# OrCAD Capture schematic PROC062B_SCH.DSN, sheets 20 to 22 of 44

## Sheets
20 19. EEPROM & PRESENCE DETECTION: size C; title: EEPROM,PRESENCE DETECTION & TEMP SENSOR
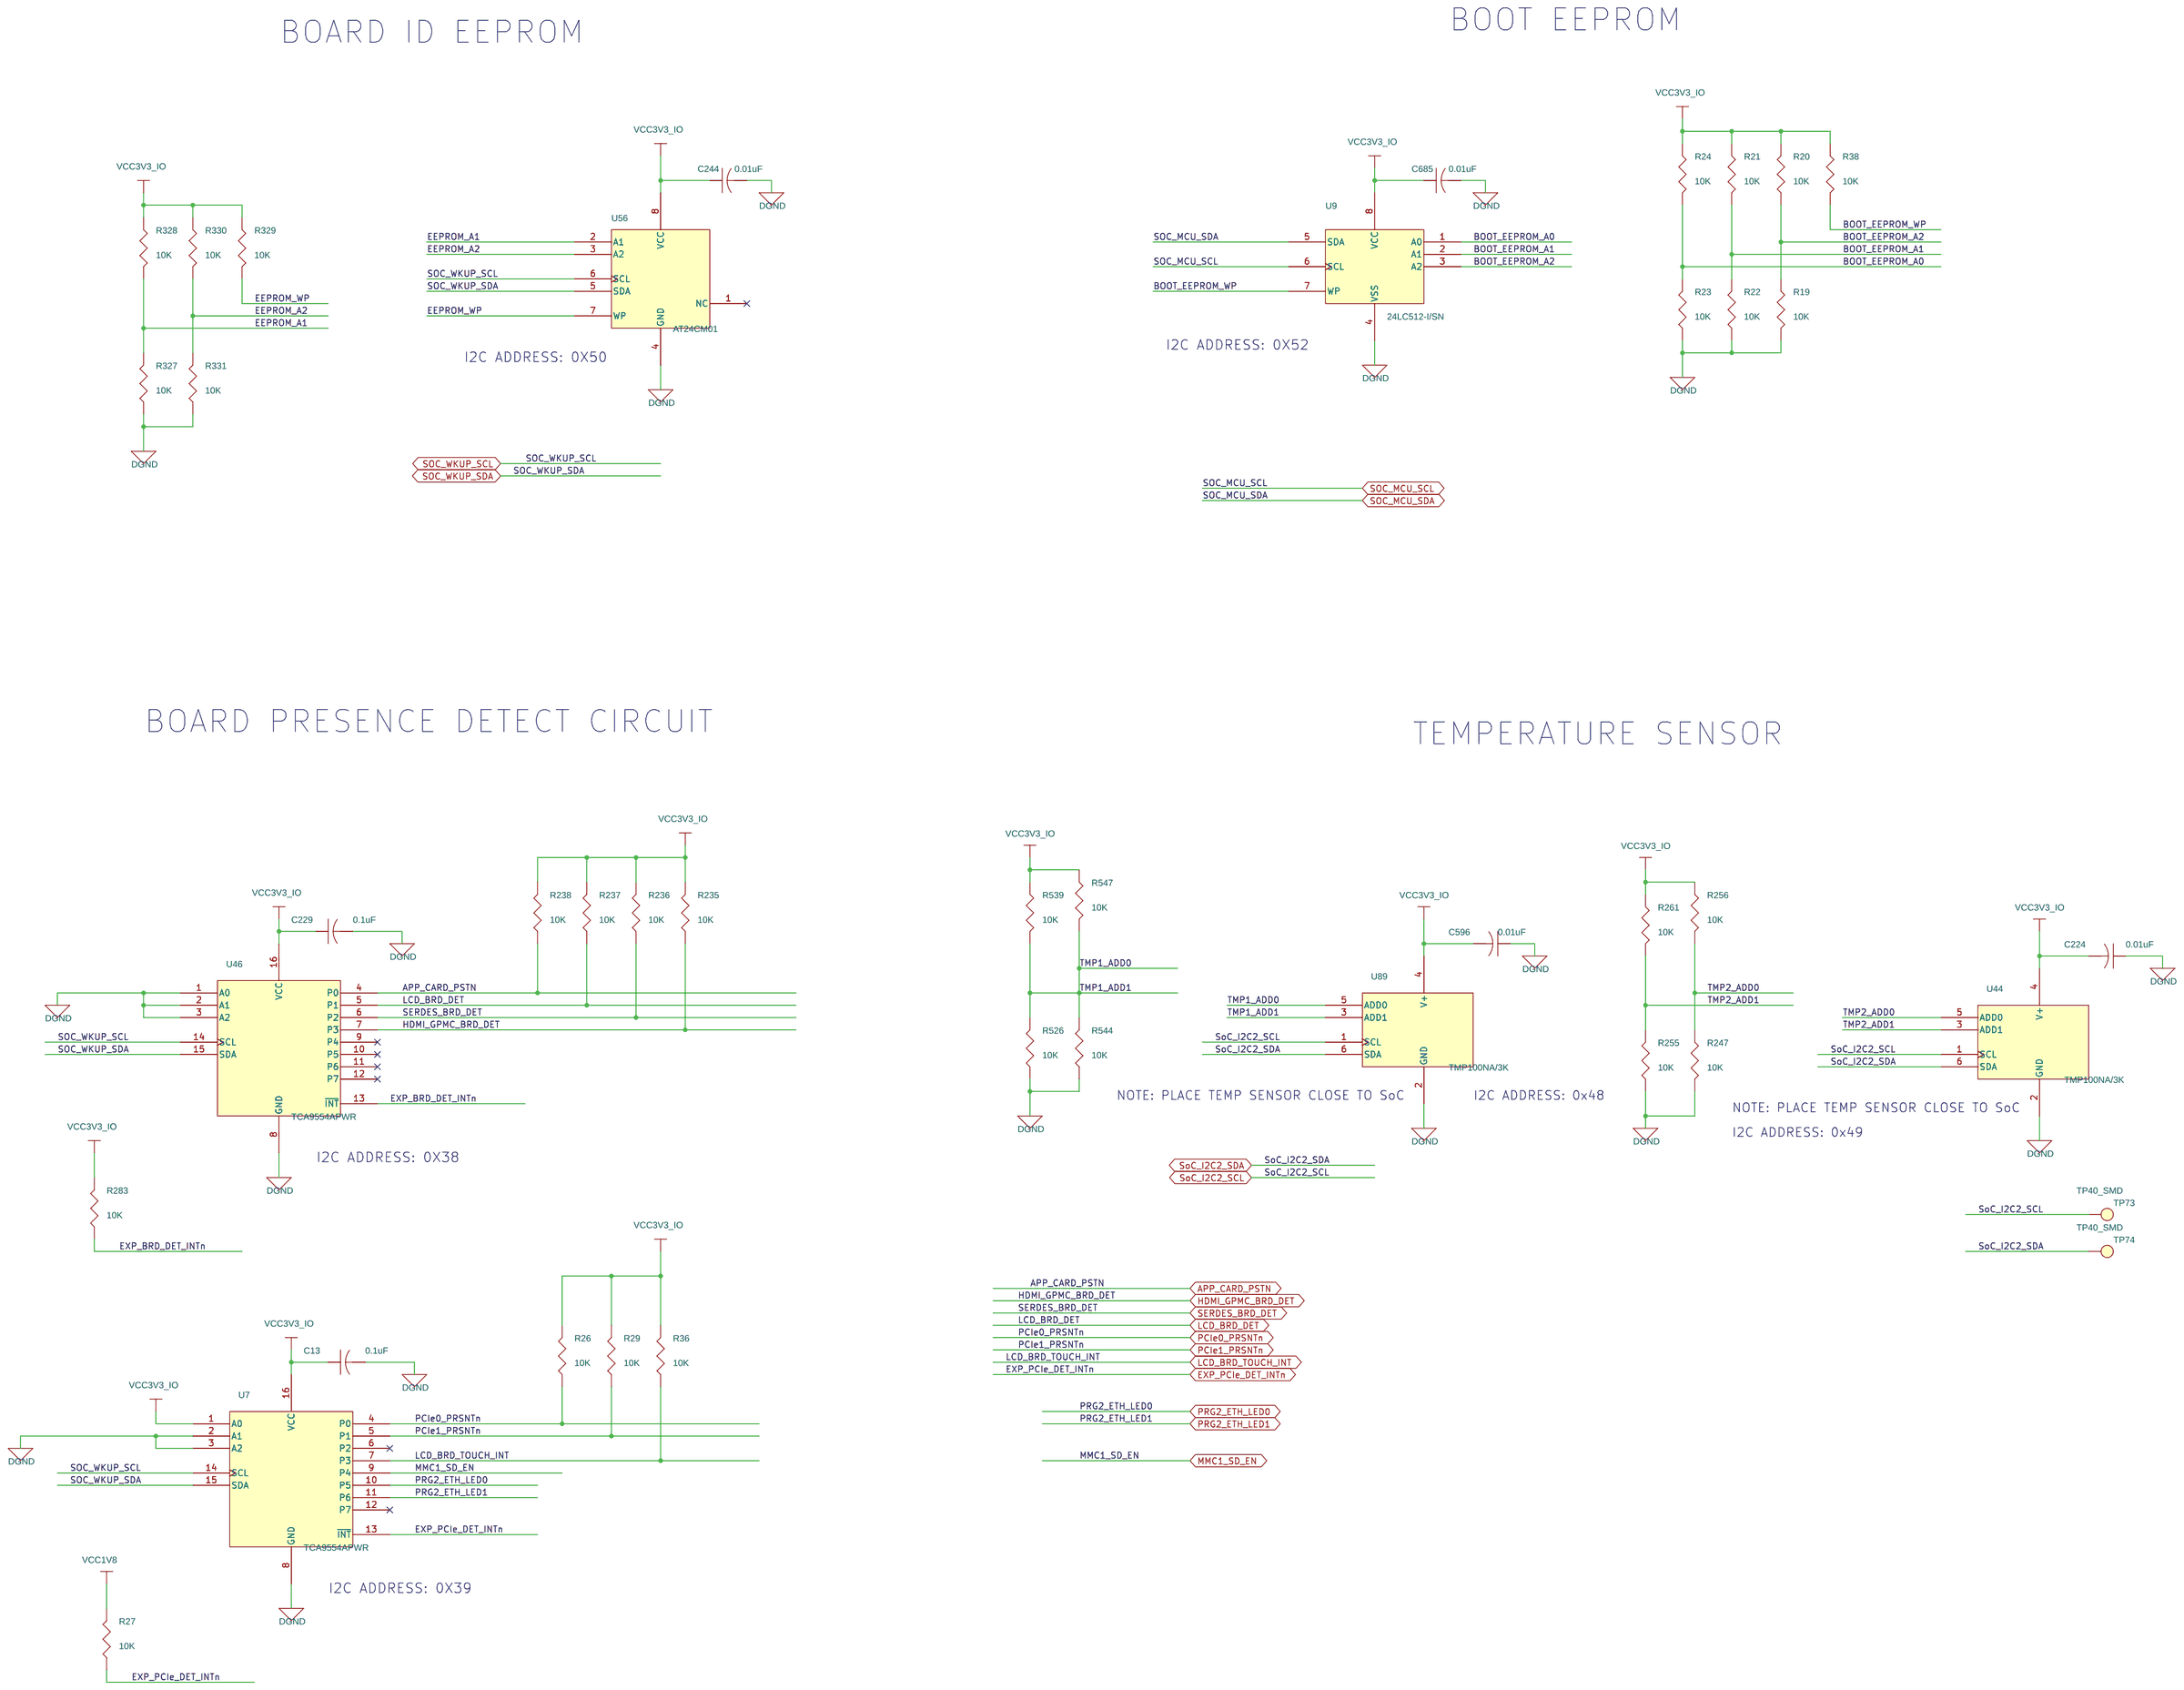
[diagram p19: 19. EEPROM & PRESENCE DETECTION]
21 20. RGMII_1 ETHERNET PHY- ICSSG: size C; title: RGMII ETHERNET PHY - ICSSG PRG2_PRU0
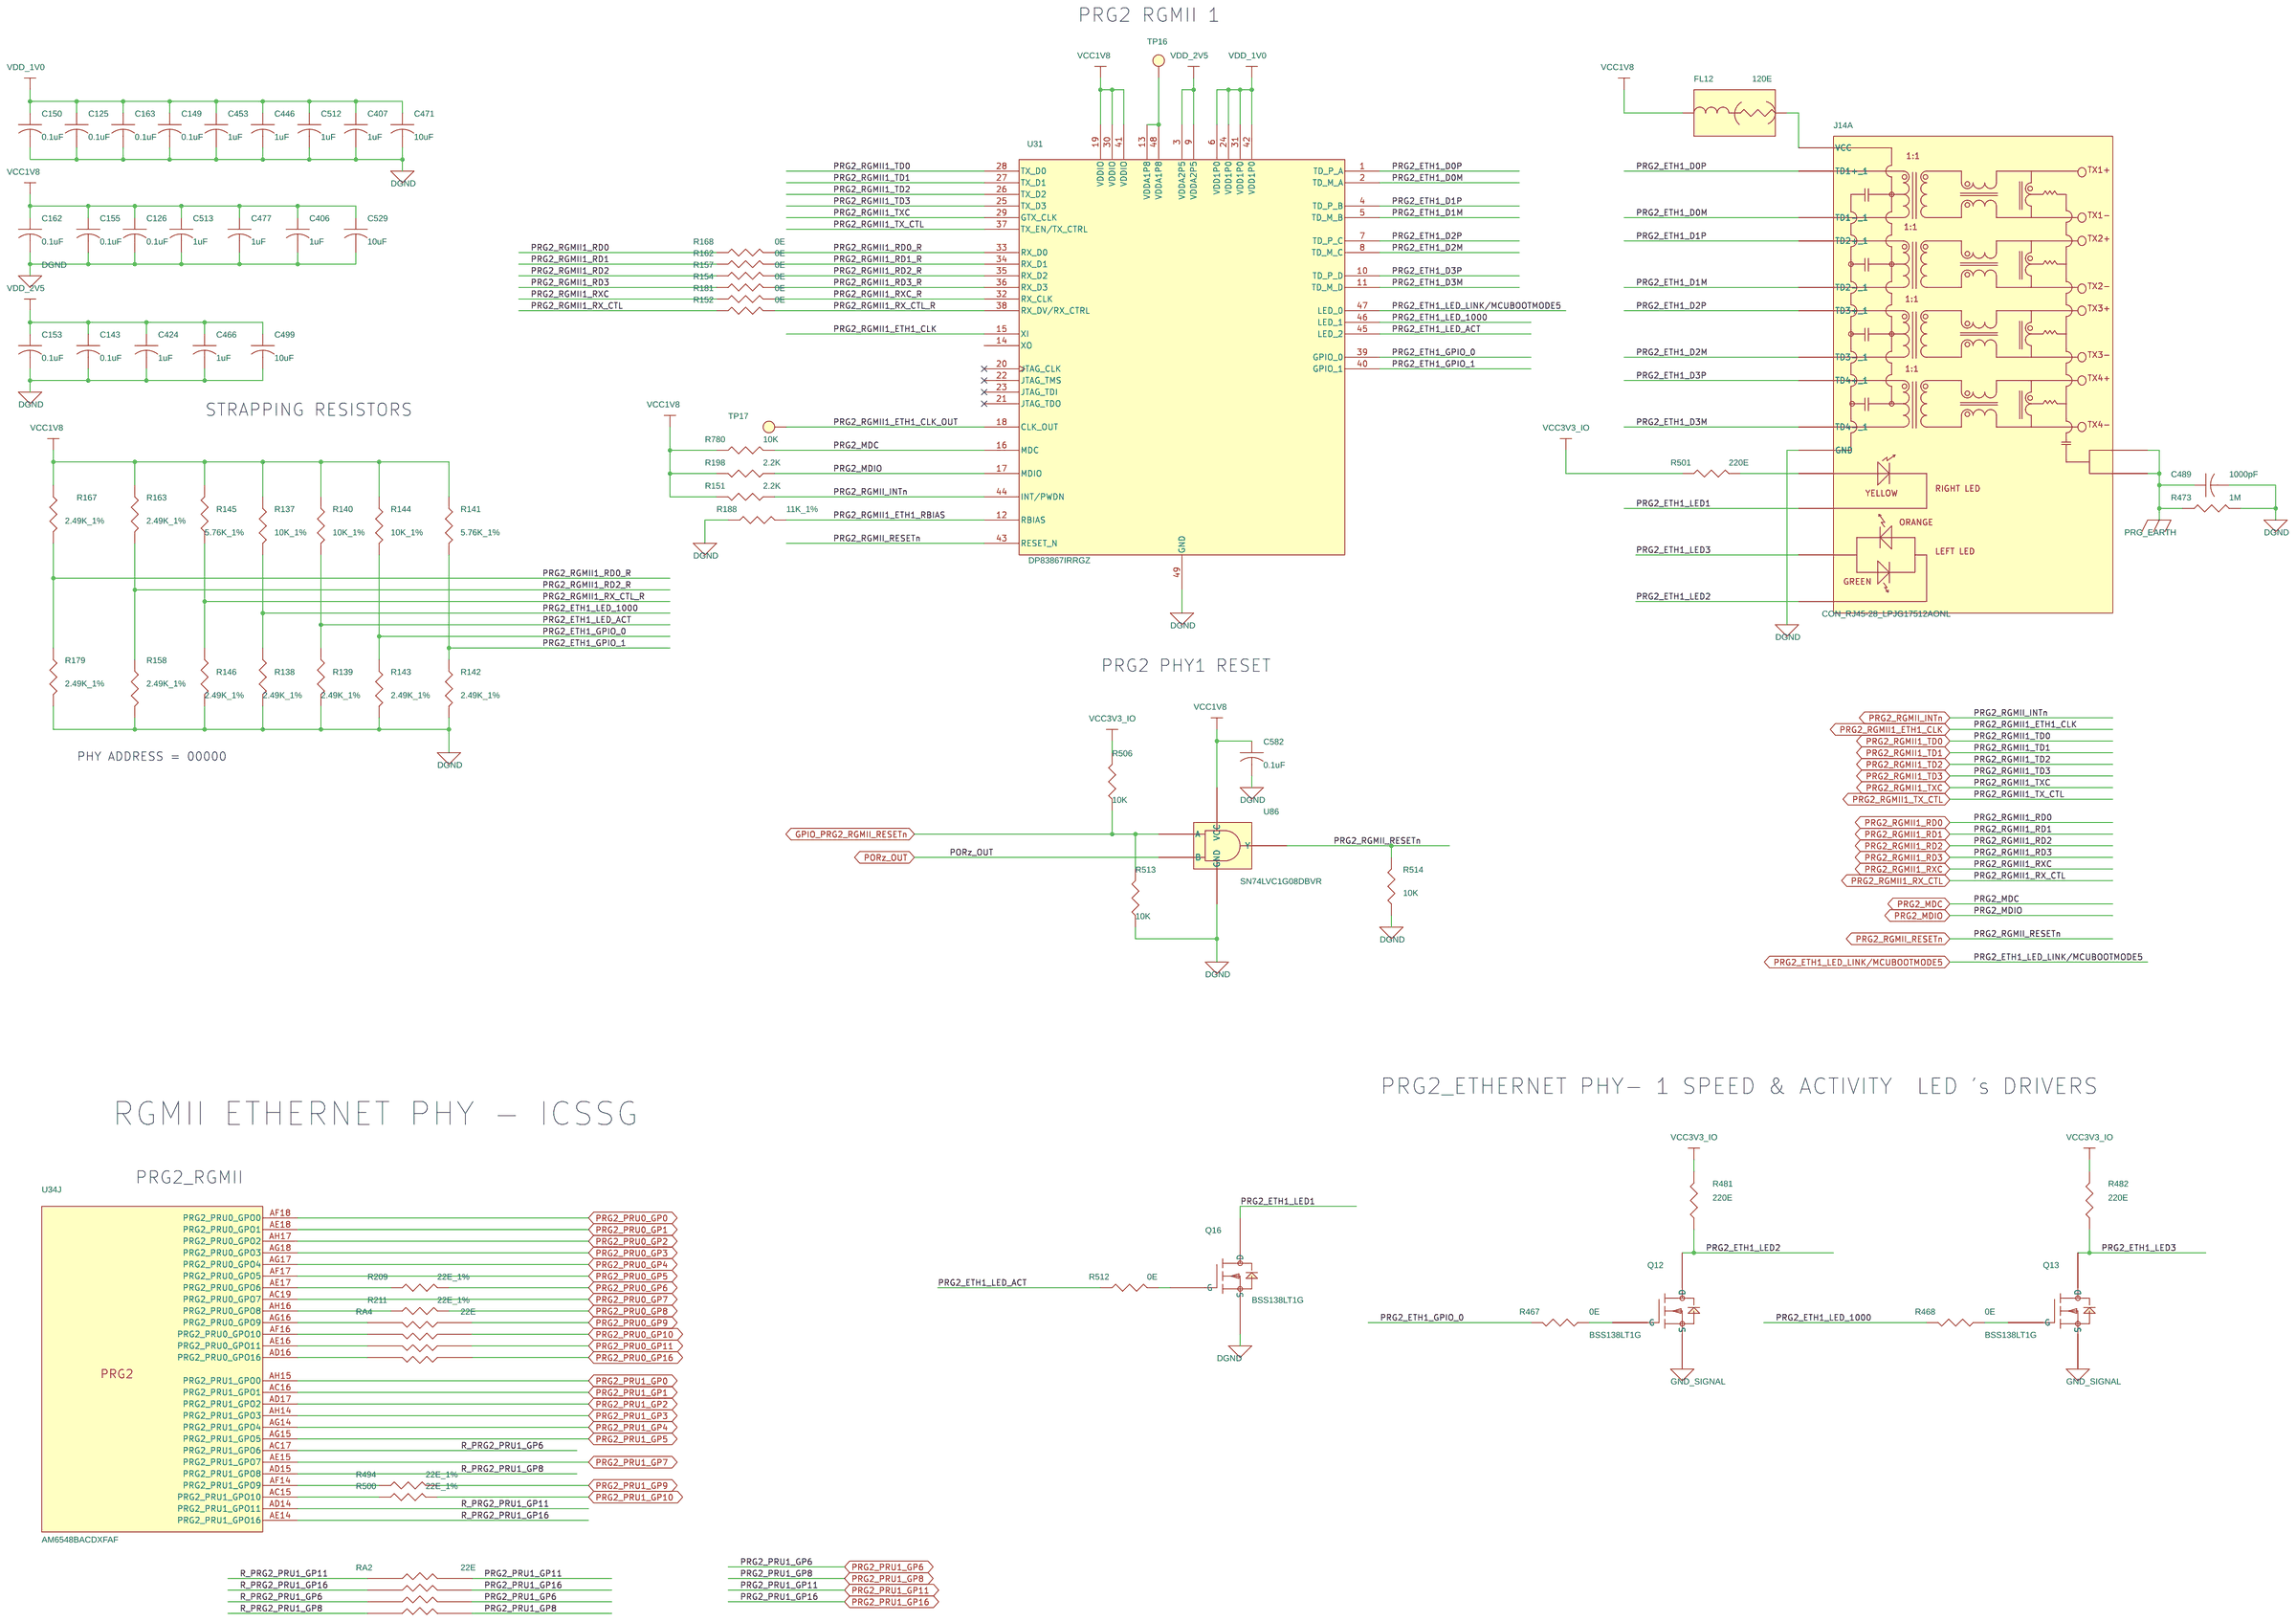
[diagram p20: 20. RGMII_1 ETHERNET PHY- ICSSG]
22 21. RGMII_2 ETHERNET PHY- ICSSG: size C; title: RGMII ETHERNET PHY - ICSSG PRG2_PRU1
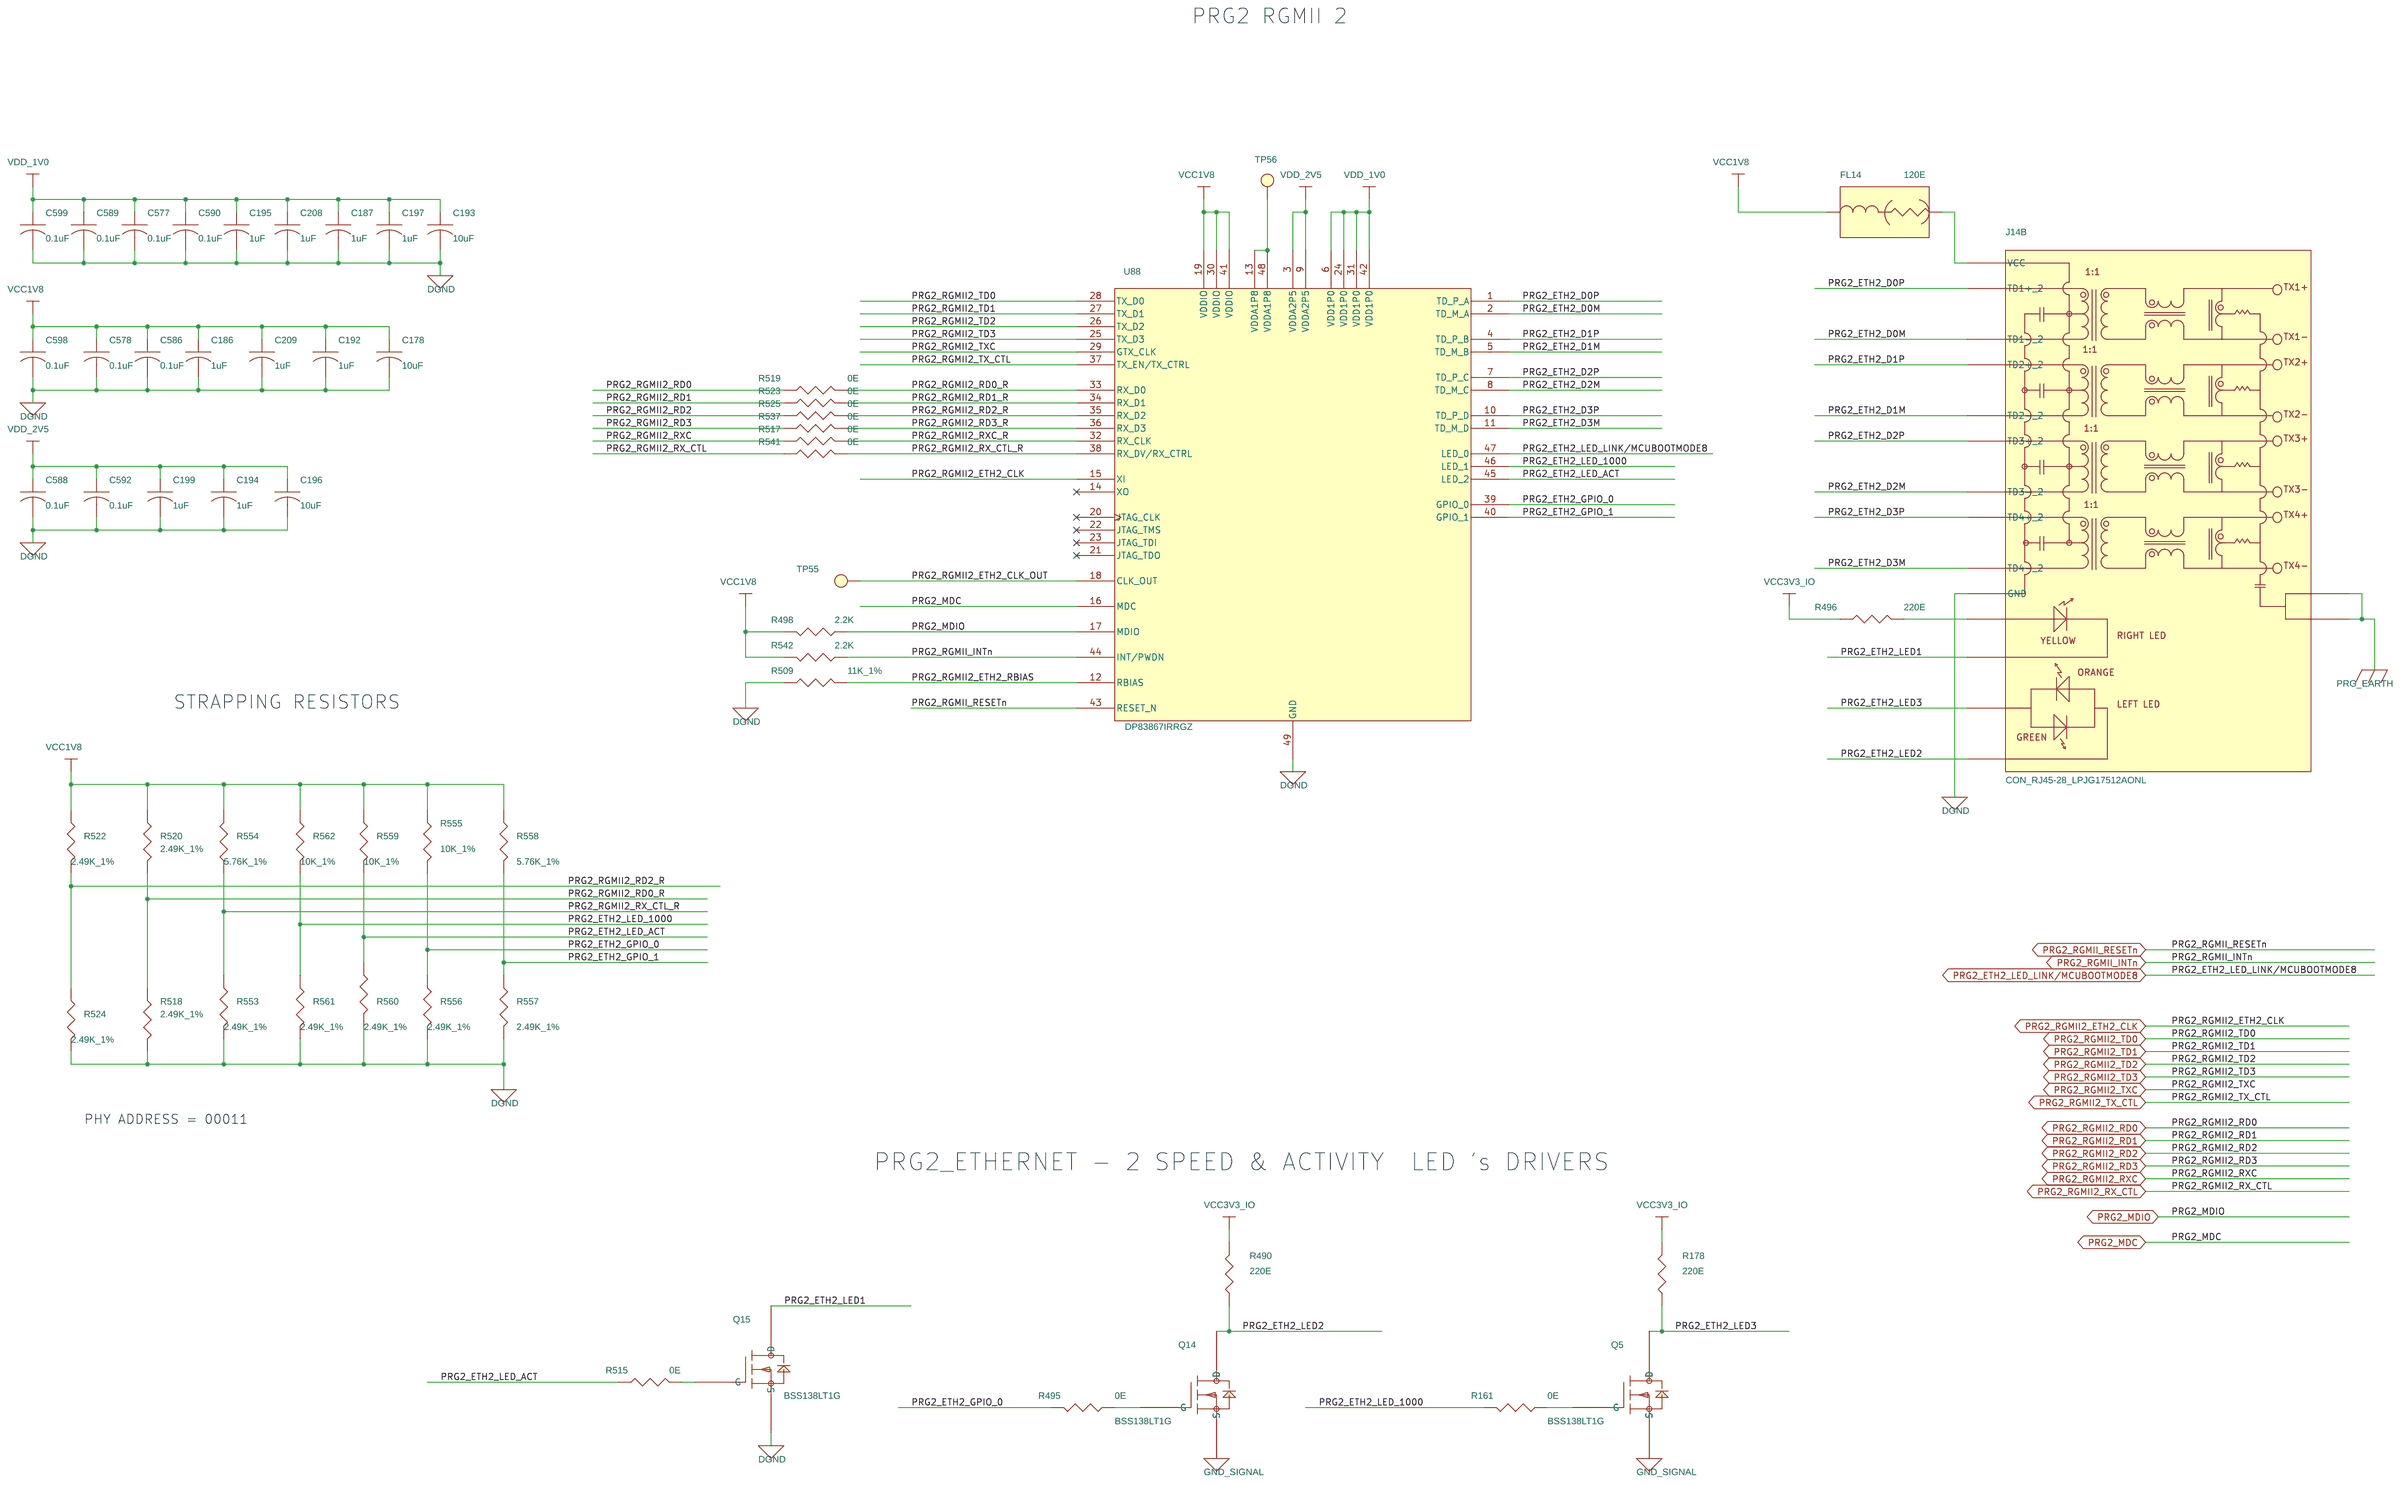
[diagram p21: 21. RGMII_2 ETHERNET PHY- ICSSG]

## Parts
sheet 16. DDR4 ECC & TERMINATIONS
U34  AM6548BACDXFAF  [BGA784_31-49_910X910_1-7]  (sections A,B,C,D,E,F,G,H,I,J,K,L,M,N,O,P,Q,R,S)
sheet 19. EEPROM & PRESENCE DETECTION
C13  0.1uF  [CAP0201_0-5]
C224  0.01uF  [CAP0201_0-5]
C229  0.1uF  [CAP0201_0-5]
C244  0.01uF  [CAP0201_0-5]
C596  0.01uF  [CAP0201_0-5]
C685  0.01uF  [CAP0201_0-5]
R19  10K  [RES0402_0-5]
R20  10K  [RES0402_0-5]
R21  10K  [RES0402_0-5]
R22  10K  [RES0402_0-5]
R23  10K  [RES0402_0-5]
R24  10K  [RES0402_0-5]
R26  10K  [RES0402_0-5]
R27  10K  [RES0402_0-5]
R29  10K  [RES0402_0-5]
R36  10K  [RES0402_0-5]
R38  10K  [RES0402_0-5]
R235  10K  [RES0402_0-5]
R236  10K  [RES0402_0-5]
R237  10K  [RES0402_0-5]
R238  10K  [RES0402_0-5]
R247  10K  [RES0402_0-5]
R255  10K  [RES0402_0-5]
R256  10K  [RES0402_0-5]
R261  10K  [RES0402_0-5]
R283  10K  [RES0402_0-5]
R327  10K  [RES0402_0-5]
R328  10K  [RES0402_0-5]
R329  10K  [RES0402_0-5]
R330  10K  [RES0402_0-5]
R331  10K  [RES0402_0-5]
R526  10K  [RES0402_0-5]
R539  10K  [RES0402_0-5]
R544  10K  [RES0402_0-5]
R547  10K  [RES0402_0-5]
TP73  TP40_SMD  [TP40_SMD]
TP74  TP40_SMD  [TP40_SMD]
U7  TCA9554APWR  [TSSOP16_25-59_205X180_1-2]
U9  24LC512-I/SN  [SOIC8_1-8]
U44  TMP100NA/3K  [SOT23-6_1-5]
U46  TCA9554APWR  [TSSOP16_25-59_205X180_1-2]
U56  AT24CM01  [TSSOP8_25-59_125X180_1-2]
U89  TMP100NA/3K  [SOT23-6_1-5]
sheet 20. RGMII_1 ETHERNET PHY- ICSSG
C125  0.1uF  [CAP0201_0-5]
C126  0.1uF  [CAP0201_0-5]
C143  0.1uF  [CAP0201_0-5]
C149  0.1uF  [CAP0201_0-5]
C150  0.1uF  [CAP0201_0-5]
C153  0.1uF  [CAP0201_0-5]
C155  0.1uF  [CAP0201_0-5]
C162  0.1uF  [CAP0201_0-5]
C163  0.1uF  [CAP0201_0-5]
C406  1uF  [CAP0402_0-75]
C407  1uF  [CAP0402_0-75]
C424  1uF  [CAP0402_0-75]
C446  1uF  [CAP0402_0-75]
C453  1uF  [CAP0402_0-75]
C466  1uF  [CAP0402_0-75]
C471  10uF  [CAP0603_1]
C477  1uF  [CAP0402_0-75]
C489  1000pF  [CAP1206]
C499  10uF  [CAP0603_1]
C512  1uF  [CAP0402_0-75]
C513  1uF  [CAP0402_0-75]
C529  10uF  [CAP0603_1]
C582  0.1uF  [CAP0201_0-5]
FL12  120E  [EMIFIL_BLM15A_0402_0-6]
Q12  BSS138LT1G  [SOT23-123]
Q13  BSS138LT1G  [SOT23-123]
Q16  BSS138LT1G  [SOT23-123]
R137  10K_1%  [RES0402_0-5]
R138  2.49K_1%  [RES0402]
R139  2.49K_1%  [RES0402]
R140  10K_1%  [RES0402_0-5]
R141  5.76K_1%  [RES0402]
R142  2.49K_1%  [RES0402]
R143  2.49K_1%  [RES0402]
R144  10K_1%  [RES0402_0-5]
R145  5.76K_1%  [RES0402]
R146  2.49K_1%  [RES0402]
R151  2.2K  [RES0402_0-5]
R152  0E  [RES0402_0-5]
R154  0E  [RES0402_0-5]
R157  0E  [RES0402_0-5]
R158  2.49K_1%  [RES0402]
R162  0E  [RES0402_0-5]
R163  2.49K_1%  [RES0402]
R167  2.49K_1%  [RES0402]
R168  0E  [RES0402_0-5]
R179  2.49K_1%  [RES0402]
R181  0E  [RES0402_0-5]
R188  11K_1%  [RES0402_0-5]
R198  2.2K  [RES0402_0-5]
R209  22E_1%  [RES0402]
R211  22E_1%  [RES0402]
R467  0E  [RES0402_0-5]
R468  0E  [RES0402_0-5]
R473  1M  [RES0603_0-75]
R481  220E  [RES0402_0-5]
R482  220E  [RES0402_0-5]
R494  22E_1%  [RES0402]
R500  22E_1%  [RES0402]
R501  220E  [RES0402_0-5]
R506  10K  [RES0402_0-5]
R512  0E  [RES0402_0-5]
R513  10K  [RES0402_0-5]
R514  10K  [RES0402_0-5]
R780  10K  [RES0201]
RA2  22E  [RESA_EXB28V_0402-4_0-5]
RA4  22E  [RESA_EXB28V_0402-4_0-5]
TP16  TP40_SMD  [TP40_SMD]
TP17  TP40_SMD  [TP40_SMD]
U31  DP83867IRRGZ  [QFN48_19-68_280X280_1]
U86  SN74LVC1G08DBVR  [SOT23-5]
sheet 21. RGMII_2 ETHERNET PHY- ICSSG
C178  10uF  [CAP0603_1]
C186  1uF  [CAP0402_0-75]
C187  1uF  [CAP0402_0-75]
C192  1uF  [CAP0402_0-75]
C193  10uF  [CAP0603_1]
C194  1uF  [CAP0402_0-75]
C195  1uF  [CAP0402_0-75]
C196  10uF  [CAP0603_1]
C197  1uF  [CAP0402_0-75]
C199  1uF  [CAP0402_0-75]
C208  1uF  [CAP0402_0-75]
C209  1uF  [CAP0402_0-75]
C577  0.1uF  [CAP0201_0-5]
C578  0.1uF  [CAP0201_0-5]
C586  0.1uF  [CAP0201_0-5]
C588  0.1uF  [CAP0201_0-5]
C589  0.1uF  [CAP0201_0-5]
C590  0.1uF  [CAP0201_0-5]
C592  0.1uF  [CAP0201_0-5]
C598  0.1uF  [CAP0201_0-5]
C599  0.1uF  [CAP0201_0-5]
FL14  120E  [EMIFIL_BLM15A_0402_0-6]
J14  CON_RJ45-28_LPJG17512AONL  [CON_RJ45-28_LPJG17512_S_R_T_25-3]  (sections A,B)
Q5  BSS138LT1G  [SOT23-123]
Q14  BSS138LT1G  [SOT23-123]
Q15  BSS138LT1G  [SOT23-123]
R161  0E  [RES0402_0-5]
R178  220E  [RES0402_0-5]
R490  220E  [RES0402_0-5]
R495  0E  [RES0402_0-5]
R496  220E  [RES0402_0-5]
R498  2.2K  [RES0402_0-5]
R509  11K_1%  [RES0402_0-5]
R515  0E  [RES0402_0-5]
R517  0E  [RES0402_0-5]
R518  2.49K_1%  [RES0402]
R519  0E  [RES0402_0-5]
R520  2.49K_1%  [RES0402]
R522  2.49K_1%  [RES0402]
R523  0E  [RES0402_0-5]
R524  2.49K_1%  [RES0402]
R525  0E  [RES0402_0-5]
R537  0E  [RES0402_0-5]
R541  0E  [RES0402_0-5]
R542  2.2K  [RES0402_0-5]
R553  2.49K_1%  [RES0402]
R554  5.76K_1%  [RES0402]
R555  10K_1%  [RES0402_0-5]
R556  2.49K_1%  [RES0402]
R557  2.49K_1%  [RES0402]
R558  5.76K_1%  [RES0402]
R559  10K_1%  [RES0402_0-5]
R560  2.49K_1%  [RES0402]
R561  2.49K_1%  [RES0402]
R562  10K_1%  [RES0402_0-5]
TP55  TP40_SMD  [TP40_SMD]
TP56  TP40_SMD  [TP40_SMD]
U88  DP83867IRRGZ  [QFN48_19-68_280X280_1]

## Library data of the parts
U34 = AM654X_BGA784: IC AM65X MICRO CONTROLLER UNIT BGA784; Chkd/date: ALVY/010721; Crtd /date: MANIRAJA/010721; Custom_Duty: 15%; Customs_HS_Code: 85423100; Distributor_name: NA; Distributor_part_number: NA; Footprint Path: Y:\MIS_DATABASE\Library\ALTIUM_TOOL\PCB_FOOTPRINTS\Altium_Footprint_Lib.PcbLib; Height: 1.63MM; Library Path: Y:\MIS_DATABASE\Library\ALTIUM_TOOL\SCHEMATICS_PARTS\MS_MICROCONTROLLER_Library.schlib; Mfr_name: TEXAS INSTRUMENTS; Mistral Part No: 141221070001; Package: BGA784; Part_type: ICS\DIGITAL\MICROCONTROLLER; Project: TI_AM65X_CP; RoHS: NA; Temperature: NA; Tolerance: NA; Voltage: NA; Wattage: NA; Weight: NA; Datasheet: Y:\MIS_DATABASE\DATASHEETS\ICS\DIGITAL\MICROCONTROLLER\MAXWELLM4.PDF
C13 C125 C126 C143 C149 C150 C153 C155 C162 C163 C229 C577 C578 C582 C586 C588-C590 C592 C598 C599 = CAP: CAP CERAMIC 0.1uF 16V 10% X5R 0201; Chkd/date: MANIRAJA/120218; Crtd /date: MANIRAJA/120218; Custom_Duty: 15%; Customs_HS_Code: 85322990; Distributor_name: DIGIKEY; Distributor_part_number: 490-16742-1-ND; Height: 0.33MM; Mfr_name: MURATA; Mfr_part_number: GRM033R61C104KE84J; Mistral Part No: 120009030072-R; Package: 0201; Part_type: CAPACITORS\CERAMIC; Project: TI_MAXIE_CPB; RoHS: RoHS; Temperature: -55°C+85°C; Tolerance: 10%; Voltage: 16V; Wattage: NA; Weight: 0.33mg; Datasheet: Y:\MIS_DATABASE\DATASHEETS\CAPACITORS\GRM033R61C104KE84.PDF
C224 C244 C596 C685 = CAP: CAP CERAMIC 0.01uF 25V 10% X5R 0201; Chkd/date: MANIRAJA/230118; Crtd /date: MANIRAJA/230118; Custom_Duty: 15%; Customs_HS_Code: 85322990; Distributor_name: DIGIKEY; Distributor_part_number: GRM033R61E103KA12J-ND; Height: 0.33MM; Mfr_name: MURATA; Mfr_part_number: GRM033R61E103KA12J; Mistral Part No: 120018010007-R; Package: 0201; Part_type: CAPACITORS\CERAMIC; Project: TI_MAXIE_CPB; RoHS: RoHS; Temperature: -55°C+85°C; Tolerance: 10%; Voltage: 25V; Wattage: NA; Weight: 0.33mg; Datasheet: Y:\MIS_DATABASE\DATASHEETS\CAPACITORS\GRM033R61E103KA12.PDF
R19-R24 R26 R27 R29 R36 R38 R235-R238 R247 R255 R256 R261 R283 R327-R331 R506 R513 R514 R526 R539 R544 R547 = RESISTOR: RES 10K 1/16W 5% 0402; Chkd/date: VASANTHA/061216; Crtd /date: MAZHAR/230805; Custom_Duty: 15%; Customs_HS_Code: 85332119; Distributor_name: DIGIKEY; Distributor_part_number: 311-10KJRCT-ND; Footprint Path: Y:\MIS_DATABASE\Library\ALTIUM_TOOL\PCB_FOOTPRINTS\Altium_Footprint_Lib.PcbLib; Height: 0.40MM; Library Path: Y:\MIS_DATABASE\Library\ALTIUM_TOOL\SCHEMATICS_PARTS\MS_DISCRETE_Library.schlib; Mfr_name: YAGEO AMERICA; Mfr_part_number: RC0402JR-0710KL; Mistral Part No: 110009030208-R; Package: 0402; Part_type: RESISTORS\FIXED; Project: HSE; RoHS: Pb-Free; Temperature: -55°C+155°C; Tolerance: 5%; Voltage: NA; Wattage: 1/16W; Weight: 0.65mg; Datasheet: Y:\MIS_DATABASE\DATASHEETS\RESISTORS\YAGEO-RC0402.PDF
TP16 TP17 TP55 TP56 TP73 TP74 = TESTPOINT: TESTPOINT CIR 40 SMD; Chkd/date: MAZHAR/190505; Crtd /date: MAZHAR/190505; Distributor_name: NA; Distributor_part_number: NA; Footprint Path: Y:\MIS_DATABASE\Library\ALTIUM_TOOL\PCB_FOOTPRINTS\Altium_Footprint_Lib.PcbLib; Height: NA; Library Path: Y:\MIS_DATABASE\Library\ALTIUM_TOOL\SCHEMATICS_PARTS\MS_DISCRETE_Library.schlib; MECHANICAL 3D STEP FILE: NA; Mfr_name: LOCAL; Mistral Part No: 130009030933; Package: SMD; Project: RAINIER-3; RoHS: NA; Temperature: NA; Tolerance: NA; Voltage: NA; Wattage: NA; Weight: NA; Datasheet: NA
U7 U46 = TCA9554APWR_TSSOP16: IC 8-BIT I2C AND SMBUS I/O EXPANDER WITH INTERRUPT O/P TSSOP16; Chkd/date: MANIRAJA/110917; Crtd /date: MANIRAJA/110917; Custom_Duty: 15%; Customs_HS_Code: 85423100; Distributor_name: DIGIKEY; Distributor_part_number: 296-28120-1-ND; Height: 1.20MM; Mfr_name: TEXAS INSTRUMENTS; Mistral Part No: 141017090007-R; Package: TSSOP16; Part_type: ICS\DIGITAL\BUSTRANSCEIVER; Project: TI_MAXIE_CPB; RoHS: RoHS; Temperature: -40°C+85°C; Tolerance: NA; Voltage: NA; Wattage: NA; Weight: 173mg; Datasheet: Y:\MIS_DATABASE\DATASHEETS\ICS\DIGITAL\BUSTRANSCEIVER\TCA9554.PDF
U9 = 24LC512-ESN_SOIC8: IC 512K I2C SERIAL EEPROM MEMORY SOIC8; Chkd/date: MANIRAJA/220817; Crtd /date: MANIRAJA/220817; Custom_Duty: 15%; Customs_HS_Code: 85423100; Distributor_name: DIGIKEY; Distributor_part_number: 24LC512-I/SN-ND; Height: 1.75MM; Mfr_name: MICROCHIP; Mistral Part No: 141117080005-R; Package: SOIC8; Part_type: ICS\DIGITAL\MEMORY; Project: TI_MAXIE_CPB; RoHS: RoHS; Temperature: -40°C+85°C; Tolerance: NA; Voltage: NA; Wattage: NA; Weight: 540mg; Datasheet: Y:\MIS_DATABASE\DATASHEETS\ICS\MEMORY\24LC512.PDF
U44 U89 = TMP100NA_3K_SOT23-6: IC TEMPERATURE SENSOR WITH I2C AND SMBUS INTERFACE SOT23-6; Chkd/date: MANIRAJA/290817; Crtd /date: MANIRAJA/290817; Custom_Duty: 15%; Customs_HS_Code: 85423100; Distributor_name: DIGIKEY; Distributor_part_number: 296-26833-1-ND; Height: 1.45MM; Library Ref: TMP100NA/3K_SOT23-6; Mfr_name: TEXAS INSTRUMENTS; Mistral Part No: 141017080030-R; Package: SOT23-6; Part_type: ICS\DIGITAL\PERIPHERAL; Project: TI_MAXIE_CPB; RoHS: RoHS; Temperature: -55°C+125°C; Tolerance: NA; Voltage: NA; Wattage: NA; Weight: 120mg; Datasheet: Y:\MIS_DATABASE\DATASHEETS\ICS\DIGITAL\PERIPHERAL\TMP10XX.PDF
U56 = AT24HC04B-TH-B_TSSOP8: IC 1MBIT I2C SERIAL EEPROM TSSOP8; Chkd/date: NAVEED/241114; Crtd /date: VASANTHA/230914; Custom_Duty: 15%; Customs_HS_Code: 85423100; Distributor_name: DIGIKEY; Distributor_part_number: AT24CM01-XHD-TCT-ND; Height: 1.20MM; Mfr_name: ATMEL; Mfr_part_number: AT24CM01-XHD-T; Mistral Part No: 141114090006-R; Package: TSSOP8; Part_type: ICS\DIGITAL\MEMORY; Project: GALILEO_EVM; RoHS: RoHS; Temperature: -40°C+85°C; Tolerance: NA; Voltage: NA; Wattage: NA; Weight: 158mg; Datasheet: Y:\MIS_DATABASE\DATASHEETS\ICS\MEMORY\AT24CM01.PDF
C186 C187 C192 C194 C195 C197 C199 C208 C209 C406 C407 C424 C446 C453 C466 C477 C512 C513 = CAP: CAP CERAMIC 1uF 16V 20% X5R 0402; Chkd/date: MANIRAJA/150218; Crtd /date: ALVY/150218; Custom_Duty: 15%; Customs_HS_Code: 85322990; Distributor_name: DIGIKEY; Distributor_part_number: 587-5514-1-ND; Footprint Path: Y:\MIS_DATABASE\Library\ALTIUM_TOOL\PCB_FOOTPRINTS\Altium_Footprint_Lib.PcbLib; Height: 0.55MM; Library Path: Y:\MIS_DATABASE\Library\ALTIUM_TOOL\SCHEMATICS_PARTS\MS_DISCRETE_Library.schlib; Mfr_name: TAIYO YUDEN; Mfr_part_number: EMK105BJ105MV-F; Mistral Part No: 120018020006-R; Package: 0402; Part_type: CAPACITORS\CERAMIC; Project: TI_MAXIE_CPB; RoHS: RoHS; Temperature: -55°C+85°C; Tolerance: 20%; Voltage: 16V; Wattage: NA; Weight: 0.65mg; Datasheet: Y:\MIS_DATABASE\DATASHEETS\CAPACITORS\EMK105BJ105MV-F.PDF
C178 C193 C196 C471 C499 C529 = CAP: CAP CERAMIC 10uF 10V 10% X5R 0603; Chkd/date: MANIRAJA/230118; Crtd /date: MANIRAJA/230118; Custom_Duty: 15%; Customs_HS_Code: 85322990; Distributor_name: DIGIKEY; Distributor_part_number: 478-10766-1-ND; Height: 0.94MM; Mfr_name: AVX CORPORATION; Mfr_part_number: 0603ZD106KAT2A; Mistral Part No: 120010080001-R; Package: 0603; Part_type: CAPACITORS\CERAMIC; Project: TI_MAXIE_CPB; RoHS: RoHS; Temperature: -55°C+85°C; Tolerance: 10%; Voltage: 10V; Wattage: NA; Weight: 2mg; Datasheet: Y:\MIS_DATABASE\DATASHEETS\CAPACITORS\AVX_MLC.PDF
C489 = CAP: CAP CERAMIC 1000pF 2KV 10% X7R 1206; Chkd/date: SHREESHAIL/291106; Crtd /date: MAZHAR/281106; Custom_Duty: 15%; Customs_HS_Code: 85322990; Distributor_name: DIGIKEY; Distributor_part_number: 478-2956-1-ND; Footprint Path: Y:\MIS_DATABASE\Library\ALTIUM_TOOL\PCB_FOOTPRINTS\Altium_Footprint_Lib.PcbLib; Height: 1.50MM; Library Path: Y:\MIS_DATABASE\Library\ALTIUM_TOOL\SCHEMATICS_PARTS\MS_DISCRETE_Library.schlib; Mfr_name: AVX CORPORATION; Mfr_part_number: 1206GC102KAT1A; Mistral Part No: 120009030147-R; Package: 1206; Part_type: CAPACITORS\CERAMIC; Project: ADR1B; RoHS: RoHS; Temperature: -55°C+125°C; Tolerance: 10%; Voltage: 2KV; Weight: NA; Datasheet: Y:\MIS_DATABASE\DATASHEETS\CAPACITORS\AVX_MLC.PDF
FL12 FL14 = EMIFILTER_IND: FERRITE CHIP 120E 1.3A 0402; Chkd/date: VASANTHA/010117; Crtd /date: CHAITHANYA/150312; Custom_Duty: 24%; Customs_HS_Code: 85437099; Distributor_name: DIGIKEY; Distributor_part_number: 490-5203-1-ND; Footprint Path: Y:\MIS_DATABASE\Library\ALTIUM_TOOL\PCB_FOOTPRINTS\Altium_Footprint_Lib.PcbLib; Height: 0.55MM; Library Path: Y:\MIS_DATABASE\Library\ALTIUM_TOOL\SCHEMATICS_PARTS\MS_FILTER_Library.schlib; Mfr_name: MURATA; Mfr_part_number: BLM15PD121SN1; Mistral Part No: 130012030043-R; Package: 0402; Part_type: MISC\FILTER; Project: GEN_3-8; RoHS: RoHS; Temperature: -55°C+125°C; Tolerance: 25%; Voltage: NA; Wattage: NA; Weight: 0.65mg; Datasheet: Y:\MIS_DATABASE\DATASHEETS\DISCRETES\INDUCTORS\BLM18K-SERIES.PDF
Q5 Q12-Q16 = MOSFET_BSS138LT1G: IC MOSFET N-CHANNEL 50V, SOT23-3; Chkd/date: VASANTHA/150416; Crtd /date: JEBRAN/060416; Custom_Duty: 15%; Customs_HS_Code: 85423100; Distributor_name: MOUSER; Distributor_part_number: 863-BSS138LT1G; Height: 1.11MM; Mfr_name: ON SEMICONDUCTOR; Mistral Part No: 142016040001-R; Package: SOT23-3; Part_type: ICS\POWER\MOSFET; Project: LRDE_ABCM; RoHS: RoHS; Temperature: -55°C+150°C; Tolerance: NA; Voltage: 50V; Wattage: NA; Weight: NA; Datasheet: Y:\MIS_DATABASE\DATASHEETS\DISCRETES\TRANSISTORS_FETS\BSS138LT1G.PDF
R137 R140 R144 R555 R559 R562 = RESISTOR: RES 10K 1/16W 1% 0402; Chkd/date: VASANTHA/201216; Crtd /date: GEETHA/290506; Custom_Duty: 15%; Customs_HS_Code: 85332119; Distributor_name: DIGIKEY; Distributor_part_number: 311-10.0KLRTR-ND; Footprint Path: Y:\MIS_DATABASE\Library\ALTIUM_TOOL\PCB_FOOTPRINTS\Altium_Footprint_Lib.PcbLib; Height: 0.40MM; Library Path: Y:\MIS_DATABASE\Library\ALTIUM_TOOL\SCHEMATICS_PARTS\MS_DISCRETE_Library.schlib; Mfr_name: YAGEO AMERICA; Mfr_part_number: RC0402FR-0710KL; Mistral Part No: 110009030220-P; Package: 0402; Part_type: RESISTORS\FIXED; Project: VOCERA; RoHS: Pb-Free; Temperature: -55°C+155°C; Tolerance: 1%; Voltage: NA; Wattage: 1/16W; Weight: 0.65mg; Datasheet: Y:\MIS_DATABASE\DATASHEETS\RESISTORS\YAGEO-RC0402.PDF
R138 R139 R142 R143 R146 R158 R163 R167 R179 R518 R520 R522 R524 R553 R556 R557 R560 R561 = RESISTOR: RES 2.49K 1/16W 1% 0402; Chkd/date: VASANTHA/270516; Crtd /date: VASANTHA/270516; Custom_Duty: 15%; Customs_HS_Code: 85332119; Distributor_name: DIGIKEY; Distributor_part_number: 311-2.49KLRCT-ND; Height: 0.40MM; Mfr_name: YAGEO AMERICA; Mfr_part_number: RC0402FR-072K49L; Mistral Part No: 110016050020-R; Package: 0402; Part_type: RESISTORS\FIXED; Project: TMDXCSKCC; RoHS: RoHS; Temperature: -55°C+155°C; Tolerance: 1%; Voltage: NA; Wattage: 1/16W; Weight: NA; Datasheet: Y:\MIS_DATABASE\DATASHEETS\RESISTORS\RC0402FR.PDF
R141 R145 R554 R558 = RESISTOR: RES 5.76K 1/10W 1% 0402; Chkd/date: MAZHAR/150709; Crtd /date: USMAN/220808; Custom_Duty: 15%; Customs_HS_Code: 85332119; Distributor_name: DIGIKEY; Distributor_part_number: P5.76KLCT-ND; Footprint Path: Y:\MIS_DATABASE\Library\ALTIUM_TOOL\PCB_FOOTPRINTS\Altium_Footprint_Lib.PcbLib; Height: 0.40MM; Library Path: Y:\MIS_DATABASE\Library\ALTIUM_TOOL\SCHEMATICS_PARTS\MS_DISCRETE_Library.schlib; Mfr_name: PANASONIC-ECG; Mfr_part_number: ERJ-2RKF5761X; Mistral Part No: 110009030945-R; Package: 0402; Part_type: RESISTORS\FIXED; Project: CPB; RoHS: RoHS; Tolerance: 1%; Wattage: 1/10W; Datasheet: Y:\MIS_DATABASE\DATASHEETS\RESISTORS\PAN-ERJSERIES.PDF
R151 R198 R498 R542 = RESISTOR: RES 2.2K 1/16W 5% 0402; Chkd/date: VASANTHA/061216; Crtd /date: BAVISH/021210; Custom_Duty: 15%; Customs_HS_Code: 85332119; Distributor_name: DIGIKEY; Distributor_part_number: 311-2.2KJRCT-ND; Footprint Path: VALUE IS VAILABLE 3 TIMES; Height: 0.40MM; Mfr_name: YAGEO AMERICA; Mfr_part_number: RC0402JR-072K2L; Mistral Part No: 110010120018-R; Package: 0402; Part_type: RESISTORS\FIXED; Project: TE4; RoHS: RoHS; Temperature: -55°C+155°C; Tolerance: 5%; Voltage: NA; Wattage: 1/16W; Weight: 0.65mg; Datasheet: Y:\MIS_DATABASE\DATASHEETS\RESISTORS\YAGEO.PDF
R152 R154 R157 R161 R162 R168 R181 R467 R468 R495 R512 R515 R517 R519 R523 R525 R537 R541 = RESISTOR: RES 0E 1/16W 0402; Chkd/date: VASANTHA/201216; Crtd /date: MUDDU/190810; Custom_Duty: 15%; Customs_HS_Code: 85332119; Distributor_name: DIGIKEY; Distributor_part_number: 541-0.0JCT-ND; Footprint Path: Y:\MIS_DATABASE\Library\ALTIUM_TOOL\PCB_FOOTPRINTS\Altium_Footprint_Lib.PcbLib; Height: 0.40MM; Library Path: Y:\MIS_DATABASE\Library\ALTIUM_TOOL\SCHEMATICS_PARTS\MS_DISCRETE_Library.schlib; Mfr_name: VISHAY; Mfr_part_number: CRCW04020000Z0ED; Mistral Part No: 110010080019-P; Package: 0402; Part_type: RESISTORS\FIXED; Project: PB_BUGBASE; RoHS: Pb-Free; Temperature: -55°C+155°C; Tolerance: NA; Voltage: NA; Wattage: 1/16W; Weight: 0.65g/1000pcs; Datasheet: Y:\MIS_DATABASE\DATASHEETS\RESISTORS\CRCW0603.PDF
R188 R509 = RESISTOR: RES 11K 1/16W 1% 0402; Chkd/date: VASANTHA/251115; Crtd /date: VASANTHA/251115; Custom_Duty: 15%; Customs_HS_Code: 85332119; Distributor_name: DIGIKEY; Distributor_part_number: 311-11.0KLRCT-ND; Height: 0.40MM; Mfr_name: YAGEO AMERICA; Mfr_part_number: RC0402FR-0711KL; Mistral Part No: 110015110012-P; Package: 0402; Part_type: RESISTORS\FIXED; Project: TI_VLAN_SWITCH; RoHS: Pb-Free; Temperature: -55°C+155°C; Tolerance: 1%; Voltage: NA; Wattage: 1/16W; Weight: 0.65mg; Datasheet: Y:\MIS_DATABASE\DATASHEETS\RESISTORS\YAGEO-RC0402.PDF
R209 R211 R494 R500 = RESISTOR: RES 22E 1/16W 1% 0402; Alternate_mfr_name_A: VISHAY; Alternate_mfr_part_number_A: CRCW040222R0FKED; Chkd/date: SUHAS/290910; Crtd /date: MAZHAR/090909; Cust_part_number: 4700-80047E; Custom_Duty: 15%; Customs_HS_Code: 85332119; Distributor_name: DIGIKEY; Distributor_name_A: DIGIKEY; Distributor_part_number: 311-22.0LRCT-ND; Distributor_part_number_A: 541-22.0LCT-ND; Height: 0.40MM; Mfr_name: YAGEO AMERICA; Mfr_part_number: RC0402FR-0722RL; Mistral Part No: 110009090004-P; Package: 0402; Part_type: RESISTORS\FIXED; Project: VMEFMCD; Remarks: In alternate datasheet it is RoHS COMPLIANT. Y:\MIS_DATABASE\DATASHEETS\RESISTORS\CRCW0402.PDF; RoHS: Pb-Free; SIGNAL_MODEL: RESISTOR_RES0402_22E_22E; Temperature: -55°C+155°C; Tolerance: 1%; Voltage: 50V; Wattage: 1/16W; Weight: 0.8g/1000pcs; Datasheet: Y:\MIS_DATABASE\DATASHEETS\RESISTORS\YAGEO-RC0402.PDF
R473 = RESISTOR: RES 1M 1/10W 5% 0603; Chkd/date: VASANTHA/060217; Crtd /date: USMAN/111207; Custom_Duty: 15%; Customs_HS_Code: 85332119; Distributor_name: DIGIKEY; Distributor_part_number: P1.0MGCT-ND; Height: 0.55MM; Mfr_name: PANASONIC-ECG; Mfr_part_number: ERJ-3GEYJ105V; Mistral Part No: 110009030413-R; Package: 0603; Part_type: RESISTORS\FIXED; Project: BSN; RoHS: RoHS; Temperature: -55°C+155°C; Tolerance: 5%; Voltage: NA; Wattage: 1/10W; Weight: 2mg; Datasheet: Y:\MIS_DATABASE\DATASHEETS\RESISTORS\PAN-ERJ-3GE.PDF
R178 R481 R482 R490 R496 R501 = RESISTOR: RES 220E 1/16W 5% 0402; Chkd/date: VASANTHA/291216; Crtd /date: GEETHA/260406; Custom_Duty: 15%; Customs_HS_Code: 85332119; Distributor_name: DIGIKEY; Distributor_part_number: P220JCT-ND; Footprint Path: Y:\MIS_DATABASE\Library\ALTIUM_TOOL\PCB_FOOTPRINTS\Altium_Footprint_Lib.PcbLib; Height: 0.40MM; Library Path: Y:\MIS_DATABASE\Library\ALTIUM_TOOL\SCHEMATICS_PARTS\MS_DISCRETE_Library.schlib; Mfr_name: PANASONIC-ECG; Mfr_part_number: ERJ-2GEJ221X; Mistral Part No: 110009030506-R; Package: 0402; Part_type: RESISTORS\FIXED; Project: RED EYE; RoHS: RoHS; Temperature: -55°C+155°C; Tolerance: 5%; Voltage: NA; Wattage: 1/16W; Weight: 0.8g/1000pcs; Datasheet: Y:\MIS_DATABASE\DATASHEETS\RESISTORS\ERJ12.PDF
R780 = RESISTOR: RES 10K 1/20W 5% 0201; Alternate_mfr_name_A: KOA SPEER; Alternate_mfr_part_number_A: RK73B1HTTC103J; Chkd/date: SUHAS/280910; Crtd /date: MUDDU/100710; Custom_Duty: 15%; Customs_HS_Code: 85332119; Distributor_name: NA; Distributor_name_A: NA; Distributor_part_number: NA; Distributor_part_number_A: NA; Height: 0.30MM; Mfr_name: NIC COMPONENTS; Mfr_part_number: NRC02J103TRF; Mistral Part No: 110010070051-R; Package: 0201; Part_type: RESISTORS\FIXED; Project: PB_BUGBASE; RoHS: RoHS; Temperature: -55°C+125°C; Tolerance: 5%; Voltage: 50V; Wattage: 1/20W; Weight: NA; Datasheet: Y:\MIS_DATABASE\DATASHEETS\RESISTORS\NRC SERIES.PDF
RA2 RA4 = RESARR_ISO4: RES ARRAY 22E 31mW 5% 0402; Chkd/date: MAZHAR/291208; Crtd /date: USMAN/261108; Distributor_name: DIGIKEY; Distributor_part_number: Y7220CT-ND; Height: 0.45MM; Mfr_name: PANASONIC-ECG; Mfr_part_number: EXB-28V220JX; Mistral Part No: 110009030021-R; Package: 0402; Part_type: RESISTORS\ARRAY; Project: KHAN_MAIN; RoHS: RoHS; Temperature: -55°C+125°C; Tolerance: 5%; Voltage: NA; Wattage: 31mW; Weight: 2mg; Datasheet: Y:\MIS_DATABASE\DATASHEETS\RESISTORS\EXB-2HV.PDF
U31 U88 = DP83867IRRGZ_VQFN48: IC HIGH IMMUNITY 10/100/1000 Mb/s ETHERNET PHY LAYER TRANSCEIVER VQFN48; Chkd/date: MANIRAJA/110817; Crtd /date: MANIRAJA/110817; Custom_Duty: 15%; Customs_HS_Code: 85423100; Distributor_name: DIGIKEY; Distributor_part_number: DP83867IRRGZT-ND; Height: 1.00MM; Mfr_name: TEXAS INSTRUMENTS; Mistral Part No: 143017080002-R; Package: VQFN48; Part_type: ICS\TELECOM\TRANSCEIVER; Project: TI_SVB_CONTROLLER CARD; RoHS: RoHS; Temperature: -40°C+85°C; Tolerance: NA; Voltage: NA; Wattage: NA; Weight: NA; Datasheet: Y:\MIS_DATABASE\DATASHEETS\ICS\DIGITAL\BUSTRANSCEIVER\DP83867I.PDF
U86 = SN74LVC1G08DBVR_SOT23-5: IC SINGLE 2-INPUT POSITIVE AND GATE SOT23-5; Chkd/date: SHREESHAIL/270906; Crtd /date: MAZHAR/270906; Custom_Duty: 15%; Customs_HS_Code: 85423100; Distributor_name: DIGIKEY; Distributor_part_number: 296-11601-1-ND; Height: 1.45MM; Mfr_name: TEXAS INSTRUMENTS; Mistral Part No: 141009030228-R; Part_type: ICS\DIGITAL\GATES; Project: SVDO_RMB_MMA; RoHS: Sb/ Br FREE; Datasheet: Y:\MIS_DATABASE\DATASHEETS\ICS\DIGITAL\GATES\SN74LVC1G08.PDF
J14 = CON_RJ45-28_LPJG17512AONL: CON JACK RJ45 28POS REGISTERED FEMALE RA TH; Chkd/date: MANIRAJA/010817; Crtd /date: MANIRAJA/010817; Custom_Duty: 24%; Customs_HS_Code: 85369090; Distributor_name: NA; Distributor_part_number: NA; Height: 25.30MM; Mfr_name: LINK-PP; Mfr_part_number: LPJG17512AONL; Mistral Part No: 150017080001-R; Package: THRU-HOLE; Part_type: CONNECTOR\JACK; Project: TI_SVB_DUT; RoHS: RoHS; Temperature: 0°C+70°C; Tolerance: NA; Voltage: NA; Wattage: NA; Weight: NA; Datasheet: Y:\MIS_DATABASE\DATASHEETS\CONNECTORS\LPJG17512AONL.PDF

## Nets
DGND: C13.2 C125.2 C126.2 C143.2 C149.2 C150.2 C153.2 C155.2 C162.2 C163.2 C178.2 C186.2 C187.2 C192.2 C193.2 C194.2 C195.2 C196.2 C197.2 C199.2 C208.2 C209.2 C224.1 C229.2 C244.2 C406.2 C407.2 C424.2 C446.2 C453.2 C466.2 C471.2 C477.2 C489.2 C499.2 C512.2 C513.2 C529.2 C577.2 C578.2 C582.2 C586.2 C588.2 C589.2 C590.2 C592.2 C596.1 C598.2 C599.2 C685.2 J14.A10(GND) J14.B10(GND) Q5.2(S) Q12.2(S) Q13.2(S) Q14.2(S) Q15.2(S) Q16.2(S) R19.2 R22.1 R23.1 R138.2 R139.2 R142.2 R143.2 R146.2 R158.2 R179.2 R188.2 R247.2 R255.1 R327.1 R331.1 R473.2 R509.2 R513.1 R514.2 R518.2 R524.2 R526.1 R544.1 R553.2 R556.2 R557.2 R560.2 R561.2 U7.2(A1) U7.3(A2) U7.8(GND) U9.4(VSS) U31.49(GND) U44.2(GND) U46.1(A0) U46.2(A1) U46.3(A2) U46.8(GND) U56.4(GND) U86.3(GND) U88.49(GND) U89.2(GND) ; also on sheet 11 12 13 14 15 16 17 18 19 23 24 25 26 27 28 29 30 31 32 33 34 35 36 37 38 39 40 41 42 43 44
VCC1V8: C126.1 C155.1 C162.1 C178.1 C186.1 C192.1 C209.1 C406.1 C477.1 C513.1 C529.1 C578.1 C582.1 C586.1 C598.1 FL12.1 FL14.1 R27.2 R137.1 R140.1 R141.1 R144.1 R145.2 R151.2 R163.1 R167.1 R198.2 R498.2 R520.1 R522.1 R542.2 R554.2 R555.1 R558.1 R559.1 R562.1 R780.1 U31.19(VDDIO) U31.30(VDDIO) U31.41(VDDIO) U86.5(VCC) U88.19(VDDIO) U88.30(VDDIO) U88.41(VDDIO) ; also on sheet 11 18 19 23 26 29 31 33 35 36 37 38 41 44
VCC3V3_IO: C13.1 C224.2 C229.1 C244.1 C596.2 C685.1 R20.2 R21.1 R24.1 R26.2 R29.2 R36.2 R38.1 R178.2 R235.2 R236.2 R237.2 R238.2 R256.1 R261.1 R283.2 R328.1 R329.1 R330.1 R481.2 R482.2 R490.2 R496.1 R501.1 R506.2 R539.1 R547.1 U7.1(A0) U7.16(VCC) U9.8(VCC) U44.4(V+) U46.16(VCC) U56.8(VCC) U89.4(V+) ; also on sheet 11 18 19 23 24 25 26 28 29 30 31 33 34 35 36 37 38 39 41 42 43 44
VDD_1V0: C125.1 C149.1 C150.1 C163.1 C187.1 C193.1 C195.1 C197.1 C208.1 C407.1 C446.1 C453.1 C471.1 C512.1 C577.1 C589.1 C590.1 C599.1 U31.6(VDD1P0) U31.24(VDD1P0) U31.31(VDD1P0) U31.42(VDD1P0) U88.6(VDD1P0) U88.24(VDD1P0) U88.31(VDD1P0) U88.42(VDD1P0) ; also on sheet 13 23 33 35 42
VDD_2V5: C143.1 C153.1 C194.1 C196.1 C199.1 C424.1 C466.1 C499.1 C588.1 C592.1 U31.3(VDDA2P5) U31.9(VDDA2P5) U88.3(VDDA2P5) U88.9(VDDA2P5) ; also on sheet 23 33 42
APP_CARD_PSTN: R238.1 U46.4(P0) ; also on sheet 33
BOOT_EEPROM_A0: R23.2 R24.2 U9.1(A0)
BOOT_EEPROM_A1: R21.2 R22.2 U9.2(A1)
BOOT_EEPROM_A2: R19.1 R20.1 U9.3(A2)
BOOT_EEPROM_WP: R38.2 U9.7(WP)
EEPROM_A1: R327.2 R328.2 U56.2(A1)
EEPROM_A2: R330.2 R331.2 U56.3(A2)
EEPROM_WP: R329.2 U56.7(WP)
EXP_BRD_DET_INTn: R283.1 U46.13(~{INT})
EXP_PCIe_DET_INTn: R27.1 U7.13(~{INT}) ; also on sheet 19
GPIO_PRG2_RGMII_RESETn: R506.1 R513.2 U86.1(A) ; also on sheet 37
HDMI_GPMC_BRD_DET: R235.1 U46.7(P3) ; also on sheet 44
LCD_BRD_DET: R237.1 U46.5(P1) ; also on sheet 35
LCD_BRD_TOUCH_INT: R36.1 U7.7(P3) ; also on sheet 35
MMC1_SD_EN: U7.9(P4) ; also on sheet 18
PCIe0_PRSNTn: R26.1 U7.4(P0) ; also on sheet 35
PCIe1_PRSNTn: R29.1 U7.5(P1) ; also on sheet 35
PORz_OUT: U86.2(B) ; also on sheet 19 25 33 34 35 44
PRG2_ETH1_D0M: J14.A2(TD1-_1) U31.2(TD_M_A)
PRG2_ETH1_D0P: J14.A1(TD1+_1) U31.1(TD_P_A)
PRG2_ETH1_D1M: J14.A4(TD2-_1) U31.5(TD_M_B)
PRG2_ETH1_D1P: J14.A3(TD2+_1) U31.4(TD_P_B)
PRG2_ETH1_D2M: J14.A6(TD3-_1) U31.8(TD_M_C)
PRG2_ETH1_D2P: J14.A5(TD3+_1) U31.7(TD_P_C)
PRG2_ETH1_D3M: J14.A8(TD4-_1) U31.11(TD_M_D)
PRG2_ETH1_D3P: J14.A7(TD4+_1) U31.10(TD_P_D)
PRG2_ETH1_GPIO_0: R143.1 R144.2 R467.2 U31.39(GPIO_0)
PRG2_ETH1_GPIO_1: R141.2 R142.1 U31.40(GPIO_1)
PRG2_ETH1_LED1: J14.A11 Q16.3(D)
PRG2_ETH1_LED2: J14.A13 Q12.3(D) R481.1
PRG2_ETH1_LED3: J14.A14 Q13.3(D) R482.1
PRG2_ETH1_LED_1000: R137.2 R138.1 R468.2 U31.46(LED_1)
PRG2_ETH1_LED_ACT: R139.1 R140.2 R512.1 U31.45(LED_2)
PRG2_ETH1_LED_LINK/MCUBOOTMODE5: U31.47(LED_0) ; also on sheet 25 34
PRG2_ETH2_D0M: J14.B2(TD1-_2) U88.2(TD_M_A)
PRG2_ETH2_D0P: J14.B1(TD1+_2) U88.1(TD_P_A)
PRG2_ETH2_D1M: J14.B4(TD2-_2) U88.5(TD_M_B)
PRG2_ETH2_D1P: J14.B3(TD2+_2) U88.4(TD_P_B)
PRG2_ETH2_D2M: J14.B6(TD3-_2) U88.8(TD_M_C)
PRG2_ETH2_D2P: J14.B5(TD3+_2) U88.7(TD_P_C)
PRG2_ETH2_D3M: J14.B8(TD4-_2) U88.11(TD_M_D)
PRG2_ETH2_D3P: J14.B7(TD4+_2) U88.10(TD_P_D)
PRG2_ETH2_GPIO_0: R495.2 R555.2 R556.1 U88.39(GPIO_0)
PRG2_ETH2_GPIO_1: R557.1 R558.2 U88.40(GPIO_1)
PRG2_ETH2_LED1: J14.B11 Q15.3(D)
PRG2_ETH2_LED2: J14.B13 Q14.3(D) R490.1
PRG2_ETH2_LED3: J14.B14 Q5.3(D) R178.1
PRG2_ETH2_LED_1000: R161.2 R561.1 R562.2 U88.46(LED_1)
PRG2_ETH2_LED_ACT: R515.1 R559.2 R560.1 U88.45(LED_2)
PRG2_ETH2_LED_LINK/MCUBOOTMODE8: U88.47(LED_0) ; also on sheet 25 34
PRG2_ETH_LED0: U7.10(P5) ; also on sheet 37
PRG2_ETH_LED1: U7.11(P6) ; also on sheet 37
PRG2_MDC: R780.2 U31.16(MDC) U88.16(MDC) ; also on sheet 29 35
PRG2_MDIO: R198.1 R498.1 U31.17(MDIO) U88.17(MDIO) ; also on sheet 29 35
PRG2_PRU0_GP0: U34.AF18(PRG2_PRU0_GPO0) ; also on sheet 29
PRG2_PRU0_GP1: U34.AE18(PRG2_PRU0_GPO1) ; also on sheet 29
PRG2_PRU0_GP2: U34.AH17(PRG2_PRU0_GPO2) ; also on sheet 29
PRG2_PRU0_GP3: U34.AG18(PRG2_PRU0_GPO3) ; also on sheet 29
PRG2_PRU0_GP4: U34.AG17(PRG2_PRU0_GPO4) ; also on sheet 29
PRG2_PRU0_GP5: U34.AF17(PRG2_PRU0_GPO5) ; also on sheet 29
PRG2_PRU0_GP6: R209.2 ; also on sheet 29
PRG2_PRU0_GP7: U34.AC19(PRG2_PRU0_GPO7) ; also on sheet 29
PRG2_PRU0_GP8: R211.2 ; also on sheet 29
PRG2_PRU0_GP9: RA4.4 ; also on sheet 29
PRG2_PRU0_GP10: RA4.3 ; also on sheet 29
PRG2_PRU0_GP11: RA4.2 ; also on sheet 29
PRG2_PRU0_GP16: RA4.1 ; also on sheet 29
PRG2_PRU1_GP0: U34.AH15(PRG2_PRU1_GPO0) ; also on sheet 29
PRG2_PRU1_GP1: U34.AC16(PRG2_PRU1_GPO1) ; also on sheet 29
PRG2_PRU1_GP2: U34.AD17(PRG2_PRU1_GPO2) ; also on sheet 29
PRG2_PRU1_GP3: U34.AH14(PRG2_PRU1_GPO3) ; also on sheet 29
PRG2_PRU1_GP4: U34.AG14(PRG2_PRU1_GPO4) ; also on sheet 29
PRG2_PRU1_GP5: U34.AG15(PRG2_PRU1_GPO5) ; also on sheet 29
PRG2_PRU1_GP6: RA2.3 ; also on sheet 29
PRG2_PRU1_GP7: U34.AE15(PRG2_PRU1_GPO7) ; also on sheet 29
PRG2_PRU1_GP8: RA2.4 ; also on sheet 29
PRG2_PRU1_GP9: R494.2 ; also on sheet 29
PRG2_PRU1_GP10: R500.2 ; also on sheet 29
PRG2_PRU1_GP11: RA2.1 ; also on sheet 29
PRG2_PRU1_GP16: RA2.2 ; also on sheet 29
PRG2_RGMII1_ETH1_CLK: U31.15(XI) ; also on sheet 36
PRG2_RGMII1_ETH1_CLK_OUT: TP17.1(TP) U31.18(CLK_OUT)
PRG2_RGMII1_ETH1_RBIAS: R188.1 U31.12(RBIAS)
PRG2_RGMII1_RD0: R168.1 ; also on sheet 29
PRG2_RGMII1_RD0_R: R167.2 R168.2 R179.1 U31.33(RX_D0)
PRG2_RGMII1_RD1: R162.1 ; also on sheet 29
PRG2_RGMII1_RD1_R: R162.2 U31.34(RX_D1)
PRG2_RGMII1_RD2: R157.1 ; also on sheet 29
PRG2_RGMII1_RD2_R: R157.2 R158.1 R163.2 U31.35(RX_D2)
PRG2_RGMII1_RD3: R154.1 ; also on sheet 29
PRG2_RGMII1_RD3_R: R154.2 U31.36(RX_D3)
PRG2_RGMII1_RX_CTL: R152.1 ; also on sheet 29
PRG2_RGMII1_RX_CTL_R: R145.1 R146.1 R152.2 U31.38(RX_DV/RX_CTRL)
PRG2_RGMII1_RXC: R181.1 ; also on sheet 29
PRG2_RGMII1_RXC_R: R181.2 U31.32(RX_CLK)
PRG2_RGMII1_TD0: U31.28(TX_D0) ; also on sheet 29
PRG2_RGMII1_TD1: U31.27(TX_D1) ; also on sheet 29
PRG2_RGMII1_TD2: U31.26(TX_D2) ; also on sheet 29
PRG2_RGMII1_TD3: U31.25(TX_D3) ; also on sheet 29
PRG2_RGMII1_TX_CTL: U31.37(TX_EN/TX_CTRL) ; also on sheet 29
PRG2_RGMII1_TXC: U31.29(GTX_CLK) ; also on sheet 29
PRG2_RGMII2_ETH2_CLK: U88.15(XI) ; also on sheet 36
PRG2_RGMII2_ETH2_CLK_OUT: TP55.1(TP) U88.18(CLK_OUT)
PRG2_RGMII2_ETH2_RBIAS: R509.1 U88.12(RBIAS)
PRG2_RGMII2_RD0: R519.1 ; also on sheet 29
PRG2_RGMII2_RD0_R: R518.1 R519.2 R520.2 U88.33(RX_D0)
PRG2_RGMII2_RD1: R523.1 ; also on sheet 29
PRG2_RGMII2_RD1_R: R523.2 U88.34(RX_D1)
PRG2_RGMII2_RD2: R525.1 ; also on sheet 29
PRG2_RGMII2_RD2_R: R522.2 R524.1 R525.2 U88.35(RX_D2)
PRG2_RGMII2_RD3: R537.1 ; also on sheet 29
PRG2_RGMII2_RD3_R: R537.2 U88.36(RX_D3)
PRG2_RGMII2_RX_CTL: R541.1 ; also on sheet 29
PRG2_RGMII2_RX_CTL_R: R541.2 R553.1 R554.1 U88.38(RX_DV/RX_CTRL)
PRG2_RGMII2_RXC: R517.1 ; also on sheet 29
PRG2_RGMII2_RXC_R: R517.2 U88.32(RX_CLK)
PRG2_RGMII2_TD0: U88.28(TX_D0) ; also on sheet 29
PRG2_RGMII2_TD1: U88.27(TX_D1) ; also on sheet 29
PRG2_RGMII2_TD2: U88.26(TX_D2) ; also on sheet 29
PRG2_RGMII2_TD3: U88.25(TX_D3) ; also on sheet 29
PRG2_RGMII2_TX_CTL: U88.37(TX_EN/TX_CTRL) ; also on sheet 29
PRG2_RGMII2_TXC: U88.29(GTX_CLK) ; also on sheet 29
PRG2_RGMII_INTn: R151.1 R542.1 U31.44(INT/PWDN) U88.44(INT/PWDN) ; also on sheet 38
PRG2_RGMII_RESETn: R514.1 U31.43(RESET_N) U86.4(Y) U88.43(RESET_N)
PRG_EARTH: C489.1 J14.SH1 J14.SH2 J14.SH3 J14.SH4 R473.1
R_PRG2_PRU1_GP6: RA2.6 U34.AC17(PRG2_PRU1_GPO6)
R_PRG2_PRU1_GP8: RA2.5 U34.AD15(PRG2_PRU1_GPO8)
R_PRG2_PRU1_GP11: RA2.8 U34.AD14(PRG2_PRU1_GPO11)
R_PRG2_PRU1_GP16: RA2.7 U34.AE14(PRG2_PRU1_GPO16)
SERDES_BRD_DET: R236.1 U46.6(P2) ; also on sheet 35
SoC_I2C2_SCL: TP73.1(TP) U44.1(SCL) U89.1(SCL) ; also on sheet 24 26 44
SoC_I2C2_SDA: TP74.1(TP) U44.6(SDA) U89.6(SDA) ; also on sheet 24 26 44
SOC_MCU_SCL: U9.6(SCL) ; also on sheet 34 35 44
SOC_MCU_SDA: U9.5(SDA) ; also on sheet 34 35 44
SOC_WKUP_SCL: U7.14(SCL) U46.14(SCL) U56.6(SCL) ; also on sheet 33 34 35 41 44
SOC_WKUP_SDA: U7.15(SDA) U46.15(SDA) U56.5(SDA) ; also on sheet 33 34 35 41 44
TMP1_ADD0: R544.2 R547.2 U89.5(ADD0)
TMP1_ADD1: R526.2 R539.2 U89.3(ADD1)
TMP2_ADD0: R247.1 R256.2 U44.5(ADD0)
TMP2_ADD1: R255.2 R261.2 U44.3(ADD1)
N5126218: J14.A12 R501.2
N5126260: TP16.1(TP) U31.13(VDDA1P8) U31.48(VDDA1P8)
N16865556: FL12.2 J14.A9(VCC)
N18115017: J14.B12 R496.2
N18115328: TP56.1(TP) U88.13(VDDA1P8) U88.48(VDDA1P8)
N18116794: Q16.1(G) R512.2
N18116818: Q12.1(G) R467.1
N18116875: Q13.1(G) R468.1
N18117332: Q15.1(G) R515.2
N18117348: Q14.1(G) R495.1
N18117389: Q5.1(G) R161.1
N18118509: R494.1 U34.AF14(PRG2_PRU1_GPO9)
N18118513: R500.1 U34.AC15(PRG2_PRU1_GPO10)
N18118517: R211.1 U34.AH16(PRG2_PRU0_GPO8)
N18118519: RA4.6 U34.AF16(PRG2_PRU0_GPO10)
N18118521: RA4.5 U34.AG16(PRG2_PRU0_GPO9)
N18118523: RA4.7 U34.AE16(PRG2_PRU0_GPO11)
N18118537: RA4.8 U34.AD16(PRG2_PRU0_GPO16)
N18118541: R209.1 U34.AE17(PRG2_PRU0_GPO6)
N24185170: FL14.2 J14.B9(VCC)

Not connected (* = marked no-connect by the designer): U7 6(P2)* 12(P7)*; U31 14(XO) 20(JTAG_CLK)* 21(JTAG_TDO)* 22(JTAG_TMS)* 23(JTAG_TDI)*; U46 9(P4)* 10(P5)* 11(P6)* 12(P7)*; U56 1(NC)*; U88 14(XO)* 20(JTAG_CLK)* 21(JTAG_TDO)* 22(JTAG_TMS)* 23(JTAG_TDI)*

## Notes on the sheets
sheet 20
- BOOT EEPROM
- BOARD ID EEPROM
- I2C ADDRESS: 0X52
- I2C ADDRESS: 0X50
- BOARD PRESENCE DETECT CIRCUIT
- TEMPERATURE SENSOR
- NOTE: PLACE TEMP SENSOR CLOSE TO SoC
- I2C ADDRESS: 0x48
- NOTE: PLACE TEMP SENSOR CLOSE TO SoC
- I2C ADDRESS: 0x49
- I2C ADDRESS: 0X38
- I2C ADDRESS: 0X39
sheet 21
- PRG2 RGMII 1
- STRAPPING RESISTORS
- PRG2 PHY1 RESET
- PHY ADDRESS = 00000
- PRG2_ETHERNET PHY- 1 SPEED & ACTIVITY  LED 's DRIVERS
- RGMII ETHERNET PHY - ICSSG
- PRG2_RGMII
sheet 22
- PRG2 RGMII 2
- STRAPPING RESISTORS
- PHY ADDRESS = 00011
- PRG2_ETHERNET - 2 SPEED & ACTIVITY  LED 's DRIVERS
